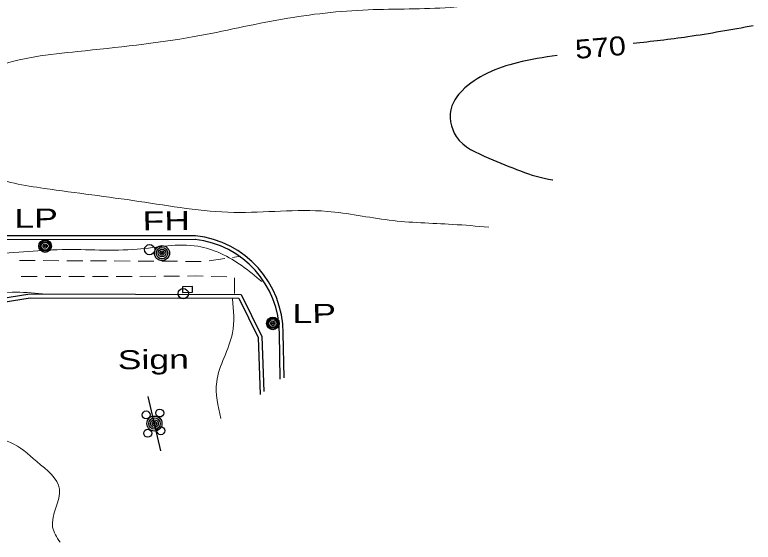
# Model space of a CAD drawing. Extents: x 2361708 to 2370558, y 6977955 to 6991887.
# Drawn here: x 2368737.1 to 2368923.8, y 6989321.3 to 6989454.7 of the extents above; entities that cross this region are included whole.
import ezdxf
from ezdxf.enums import TextEntityAlignment as Align

# ---------------------------------------------------------------- set-up
doc = ezdxf.new("R2010")
doc.units = 0
doc.header["$LTSCALE"] = 1.9
for name, color, linetype, lineweight in [('13', 7, 'Continuous', 13), ('2', 7, 'Continuous', 25), ('20', 7, 'Continuous', 25), ('21', 7, 'Continuous', 25), ('23', 7, 'Continuous', 25), ('31', 7, 'Continuous', 13), ('35', 7, 'Continuous', 13), ('7', 7, 'Continuous', 25)]:
    doc.layers.add(name, color=color, linetype=linetype, lineweight=lineweight)

msp = doc.modelspace()

# ---------------------------------------------------------------- linework, layer by layer
at = {"layer": '13'}
for p, q in [((2368742.268, 6989392.564), (2368738.268, 6989392.576)), ((2368748.269, 6989392.531), (2368744.268, 6989392.553)), ((2368754.27, 6989392.509), (2368750.269, 6989392.52)), ((2368760.27, 6989392.486), (2368756.269, 6989392.497)), ((2368766.27, 6989392.452), (2368762.27, 6989392.474)), ((2368772.271, 6989392.419), (2368768.271, 6989392.441)), ((2368778.272, 6989392.387), (2368774.271, 6989392.409)), ((2368784.272, 6989392.353), (2368780.272, 6989392.375)), ((2368790.216, 6989393.081), (2368786.261, 6989392.513)), ((2368794.17, 6989393.648), (2368792.193, 6989393.359)), ((2368738.756, 6989388.55), (2368742.757, 6989388.548)), ((2368768.758, 6989388.556), (2368772.757, 6989388.594)), ((2368774.757, 6989388.613), (2368778.757, 6989388.651)), ((2368786.758, 6989388.577), (2368790.76, 6989388.445)), ((2368744.756, 6989388.547), (2368748.757, 6989388.536)), ((2368750.757, 6989388.535), (2368754.758, 6989388.523)), ((2368756.758, 6989388.522), (2368760.758, 6989388.51)), ((2368792.622, 6989388.243), (2368792.7, 6989384.243))]:
    msp.add_line(p, q, dxfattribs=at)
for points in [[(2368780.757, 6989388.67), (2368782.807, 6989388.7), (2368784.758, 6989388.638)], [(2368762.758, 6989388.509), (2368763.688, 6989388.508), (2368766.758, 6989388.537)]]:
    msp.add_lwpolyline(points, dxfattribs=at)
at = {"layer": '2'}
for p, q in [((2368804.226, 6989362.622), (2368803.996, 6989374.191)), ((2368805.184, 6989362.931), (2368804.956, 6989374.21))]:
    msp.add_line(p, q, dxfattribs=at)
for points in [[(2368782.79, 6989398.83), (2368685.726, 6989398.816), (2368587.383, 6989398.57), (2368461.214, 6989397.859), (2368404.62, 6989398.04)], [(2368782.79, 6989397.87), (2368685.725, 6989397.856), (2368587.383, 6989397.61), (2368461.213, 6989396.899), (2368404.619, 6989397.08)], [(2368646.379, 6989368.92), (2368740.948, 6989384.151), (2368794.382, 6989383.99), (2368799.564, 6989373.349), (2368800.077, 6989359.433)], [(2368646.528, 6989367.972), (2368741.028, 6989383.192), (2368793.781, 6989383.034), (2368798.616, 6989373.11), (2368799.143, 6989358.714)]]:
    msp.add_lwpolyline(points, dxfattribs=at)
for radius in [24.748, 23.788]:
    msp.add_arc((2368780.208, 6989374.217), radius, 359.98237, 84.01091, dxfattribs=at)
at = {"layer": '20'}
for centre, radius in [((2368744.783, 6989396.248), 1.6), ((2368744.783, 6989396.248), 1.3), ((2368744.783, 6989396.248), 1), ((2368744.783, 6989396.248), 0.539), ((2368744.783, 6989396.248), 0.192), ((2368771.203, 6989395.34), 1.3), ((2368774.322, 6989394.469), 1.9), ((2368774.322, 6989394.469), 1.442), ((2368774.322, 6989394.469), 0.973), ((2368774.322, 6989394.469), 0.539), ((2368774.322, 6989394.469), 0.192), ((2368802.352, 6989376.695), 1.6), ((2368802.352, 6989376.695), 1.3), ((2368802.352, 6989376.695), 1), ((2368802.352, 6989376.695), 0.539), ((2368802.352, 6989376.695), 0.192)]:
    msp.add_circle(centre, radius, dxfattribs=at)
at = {"layer": '21'}
msp.add_line((2368774.007, 6989344.494), (2368770.837, 6989358.225), dxfattribs=at)
for radius in [1.9, 1.442, 0.973, 0.539, 0.192]:
    msp.add_circle((2368772.422, 6989351.359), radius, dxfattribs=at)
at = {"layer": '23'}
msp.add_lwpolyline([(2368782.012, 6989386.032), (2368779.493, 6989385.948), (2368779.537, 6989384.488), (2368782.056, 6989384.572)], close=True, dxfattribs=at)
msp.add_circle((2368779.71, 6989384.21), 1.3, dxfattribs=at)
at = {"layer": '31', "lineweight": 25}
for points in [[(2368923.812, 6989451.945), (2368907.308, 6989449.148), (2368893.443, 6989447.445)], [(2368874.281, 6989444.463), (2368864.148, 6989442.587), (2368850.195, 6989435.533), (2368847.611, 6989431.689), (2368848.735, 6989423.909), (2368856.997, 6989418.507), (2368873.06, 6989413), (2368873.18, 6989412.981)]]:
    msp.add_spline(points, degree=3, dxfattribs=at)
at = {"layer": '35'}
for points in [[(2368861.569, 6989458.233), (2368847.184, 6989456.575), (2368826.429, 6989455.978), (2368804.79, 6989453.632), (2368782.501, 6989449.21), (2368753.065, 6989445.449), (2368731.782, 6989441.416), (2368719.899, 6989433.373), (2368717.097, 6989427.186), (2368719.967, 6989422.003), (2368729.95, 6989414.378), (2368744.564, 6989410.827), (2368768.457, 6989407.544), (2368792.514, 6989404.773), (2368816.093, 6989405.017), (2368831.765, 6989402.797), (2368847.806, 6989401.719), (2368856.963, 6989401.036)], [(2368799.541, 6989387.319), (2368794.573, 6989391.242), (2368783.376, 6989396.185), (2368768.042, 6989395.45), (2368749.052, 6989395.339), (2368729.821, 6989394.266), (2368719.565, 6989392.818), (2368715.042, 6989388.845), (2368718.083, 6989385.623), (2368725.491, 6989383.824), (2368736.434, 6989384.578), (2368744.098, 6989384.191)], [(2368792.143, 6989382.918), (2368792.145, 6989374.268), (2368788.152, 6989361.899), (2368789.191, 6989352.629)], [(2368682.846, 6989373.647), (2368683.712, 6989365.575), (2368689.488, 6989359.73), (2368701.646, 6989356.826), (2368711.937, 6989354.773), (2368720.94, 6989349.169), (2368736.015, 6989346.592), (2368742.702, 6989341.755), (2368748.398, 6989334.8), (2368746.68, 6989325.193), (2368748.546, 6989321.35)]]:
    msp.add_spline(points, degree=3, dxfattribs=at)
at = {"layer": '7'}
for centre in [(2368773.757, 6989354.022), (2368770.331, 6989353.539), (2368770.735, 6989348.913), (2368774.039, 6989349.544)]:
    msp.add_circle(centre, 1, dxfattribs=at)

# ---------------------------------------------------------------- texts
at = {"layer": '20', "width": 1.4}
for s, p in [('  LP', (2368732.039, 6989400.797)), ('  FH', (2368764.447, 6989400.146)), ('  LP', (2368802.352, 6989376.695)), ('Sign', (2368763.161, 6989365.072))]:
    msp.add_text(s, height=4.8, rotation=0.545, dxfattribs=at).set_placement(p)
at = {"layer": '31', "width": 1.2}
msp.add_text(' 570 ', height=4.8, rotation=4.758, dxfattribs=at).set_placement((2368885.379, 6989444.092), align=Align.CENTER)

doc.saveas('drawing.dxf')
